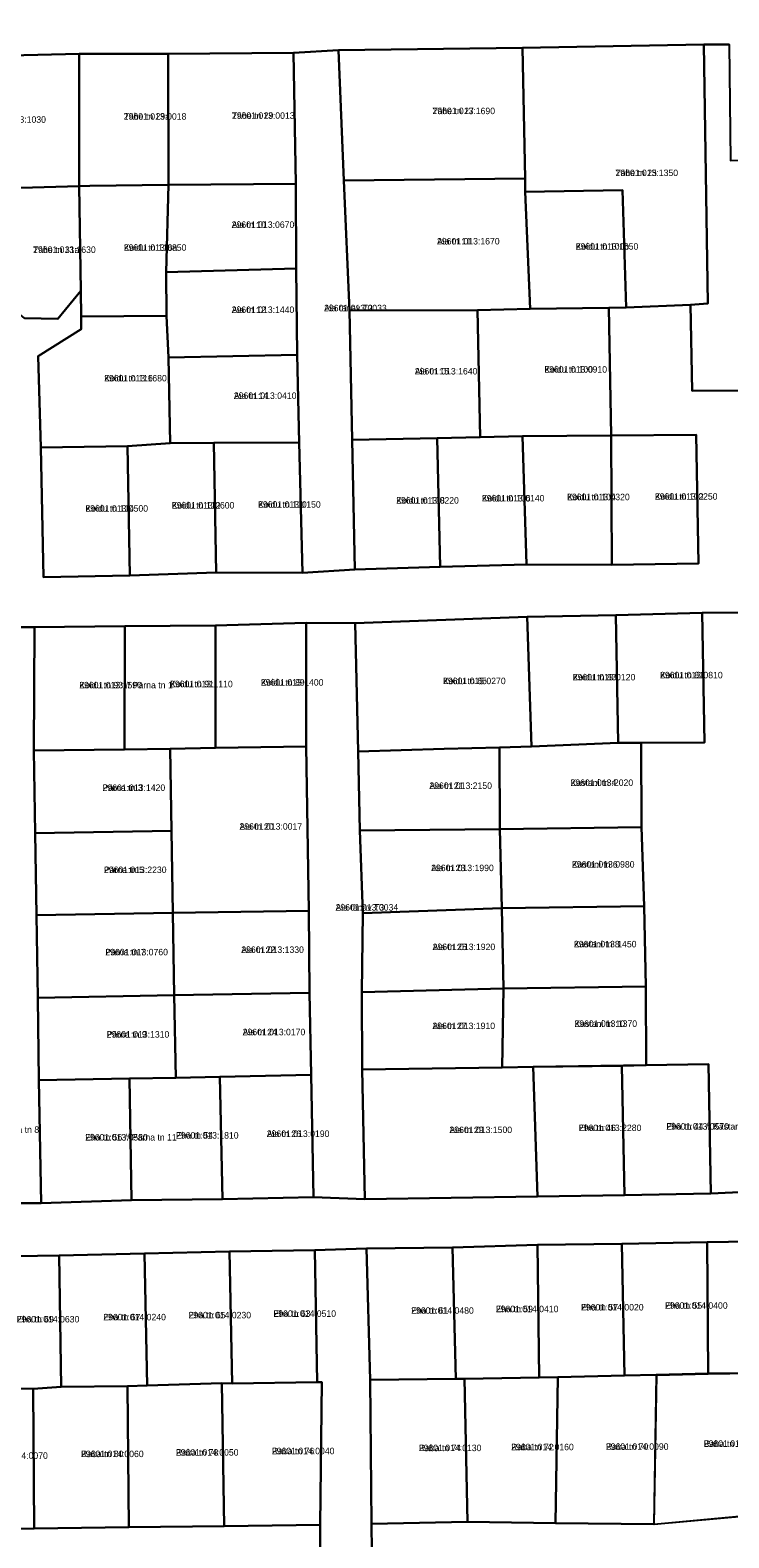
# Model space of a CAD drawing. Extents: x 518839 to 525192, y 6573164 to 6576561.
# Drawn here: x 523514.2 to 523676, y 6573652.7 to 6574001.8 of the extents above; entities that cross this region are included whole.
import ezdxf

# ---------------------------------------------------------------- set-up
doc = ezdxf.new("R2010")
doc.units = 0
for name, color, linetype in [('L_AADRESS', 7, 'Continuous'), ('PIIR', 7, 'Continuous'), ('TUNNUS', 7, 'Continuous')]:
    doc.layers.add(name, color=color, linetype=linetype)

msp = doc.modelspace()

# ---------------------------------------------------------------- linework, layer by layer
at = {"layer": 'PIIR'}
for points in [[(523676.04, 6573998.47), (523670.16, 6573998.46), (523628.17, 6573997.67), (523585.64, 6573997.1), (523575.15, 6573996.53), (523546.14, 6573996.29), (523525.52, 6573996.29), (523480.74, 6573995.19), (523455.07, 6573994.57), (523435.27, 6573993.85), (523414.5, 6573993.67), (523371.79, 6573992.85), (523370.33, 6574007.54)], [(523512.9, 6573935.07), (523520.6, 6573934.94), (523525.92, 6573941.42), (523526.01, 6573935.47), (523525.98, 6573932.52), (523516.07, 6573926.28), (523516.7, 6573905.14), (523517.3, 6573875.11), (523537.3, 6573875.48), (523557.26, 6573876.22), (523577.26, 6573876.13), (523589.39, 6573876.9), (523609.17, 6573877.54), (523629.13, 6573878.07), (523648.89, 6573878), (523669, 6573878.25), (523668.45, 6573908.07), (523648.73, 6573907.92), (523648.2, 6573937.46), (523652.2, 6573937.52), (523667.09, 6573938.18), (523667.5, 6573918.29), (523684.56, 6573918.33)], [(523680.81, 6573866.98), (523669.79, 6573866.9), (523649.8, 6573866.3), (523629.31, 6573865.94), (523589.48, 6573864.46), (523578.15, 6573864.54), (523557.15, 6573863.96), (523536.12, 6573863.76), (523515.24, 6573863.54), (523505.5, 6573863.51)], [(523507.79, 6573730.18), (523516.72, 6573730.15), (523537.69, 6573730.88), (523558.72, 6573731.15), (523579.85, 6573731.54), (523591.71, 6573731.11), (523631.71, 6573731.73), (523651.79, 6573732.03), (523671.79, 6573732.4), (523683.56, 6573732.98)], [(523690.66, 6573721.47), (523670.95, 6573721.16), (523651.22, 6573720.81), (523631.65, 6573720.51), (523611.99, 6573719.95), (523592.12, 6573719.66), (523580.11, 6573719.33), (523560.38, 6573718.97), (523540.72, 6573718.56), (523520.95, 6573718.1), (523500.82, 6573717.74)]]:
    msp.add_lwpolyline(points, dxfattribs=at)
for points in [[(523575.15, 6573996.53), (523585.64, 6573997.1), (523586.81, 6573966.96), (523588.13, 6573936.85), (523588.77, 6573906.88), (523589.39, 6573876.9), (523577.26, 6573876.13), (523576.53, 6573906.29), (523576.07, 6573926.61), (523575.82, 6573946.61), (523575.71, 6573966.2)], [(523585.64, 6573997.1), (523628.17, 6573997.67), (523628.8, 6573967.45), (523586.81, 6573966.96)], [(523651.37, 6573964.72), (523628.86, 6573964.36), (523628.8, 6573967.45), (523628.17, 6573997.67), (523670.16, 6573998.46), (523671.15, 6573938.46), (523667.09, 6573938.18), (523652.2, 6573937.52)], [(523670.16, 6573998.46), (523676.04, 6573998.47), (523676.34, 6573971.58), (523712.69, 6573972.67), (523712.7, 6573966.98), (523713.63, 6573939.28), (523699.65, 6573938.45), (523700.01, 6573925.48), (523684.56, 6573918.33), (523667.5, 6573918.29), (523667.09, 6573938.18), (523671.15, 6573938.46)], [(523480.74, 6573995.19), (523525.52, 6573996.29), (523525.53, 6573965.66), (523503.85, 6573965.03), (523481.7, 6573964.38)], [(523546.14, 6573996.29), (523546.24, 6573965.93), (523528.03, 6573965.71), (523525.53, 6573965.66), (523525.52, 6573996.29)], [(523575.15, 6573996.53), (523575.71, 6573966.2), (523546.24, 6573965.93), (523546.14, 6573996.29)], [(523505.33, 6573941.1), (523503.85, 6573965.03), (523525.53, 6573965.66), (523525.92, 6573941.42), (523520.6, 6573934.94), (523512.9, 6573935.07)], [(523525.92, 6573941.42), (523525.53, 6573965.66), (523528.03, 6573965.71), (523546.24, 6573965.93), (523545.71, 6573945.77), (523545.8, 6573935.63), (523526.01, 6573935.47)], [(523575.82, 6573946.61), (523545.71, 6573945.77), (523546.24, 6573965.93), (523575.71, 6573966.2)], [(523586.81, 6573966.96), (523628.8, 6573967.45), (523628.86, 6573964.36), (523629.98, 6573937.21), (523617.78, 6573936.97), (523588.13, 6573936.85)], [(523628.86, 6573964.36), (523651.37, 6573964.72), (523652.2, 6573937.52), (523648.2, 6573937.46), (523629.98, 6573937.21)], [(523545.8, 6573935.63), (523545.71, 6573945.77), (523575.82, 6573946.61), (523576.07, 6573926.61), (523546.27, 6573925.97)], [(523516.07, 6573926.28), (523525.98, 6573932.52), (523526.01, 6573935.47), (523545.8, 6573935.63), (523546.27, 6573925.97), (523546.61, 6573906.17), (523536.75, 6573905.46), (523516.7, 6573905.14)], [(523588.13, 6573936.85), (523617.78, 6573936.97), (523618.4, 6573907.5), (523608.47, 6573907.29), (523588.77, 6573906.88)], [(523618.4, 6573907.5), (523617.78, 6573936.97), (523629.98, 6573937.21), (523648.2, 6573937.46), (523648.73, 6573907.92), (523628.19, 6573907.76)], [(523546.61, 6573906.17), (523546.27, 6573925.97), (523576.07, 6573926.61), (523576.53, 6573906.29), (523556.71, 6573906.21)], [(523546.61, 6573906.17), (523556.71, 6573906.21), (523557.26, 6573876.22), (523537.3, 6573875.48), (523536.75, 6573905.46)], [(523556.71, 6573906.21), (523576.53, 6573906.29), (523577.26, 6573876.13), (523557.26, 6573876.22)], [(523588.77, 6573906.88), (523608.47, 6573907.29), (523609.17, 6573877.54), (523589.39, 6573876.9)], [(523608.47, 6573907.29), (523618.4, 6573907.5), (523628.19, 6573907.76), (523629.13, 6573878.07), (523609.17, 6573877.54)], [(523628.19, 6573907.76), (523648.73, 6573907.92), (523648.89, 6573878), (523629.13, 6573878.07)], [(523648.73, 6573907.92), (523668.45, 6573908.07), (523669, 6573878.25), (523648.89, 6573878)], [(523517.3, 6573875.11), (523516.7, 6573905.14), (523526.75, 6573905.28), (523536.75, 6573905.46), (523537.3, 6573875.48)], [(523557.15, 6573863.96), (523578.15, 6573864.54), (523578.13, 6573835.94), (523557.1, 6573835.59)], [(523578.15, 6573864.54), (523589.48, 6573864.46), (523590.14, 6573834.75), (523590.58, 6573816.5), (523591.2, 6573797.32), (523591.04, 6573779.03), (523591.09, 6573761.1), (523591.71, 6573731.11), (523579.85, 6573731.54), (523579.26, 6573759.91), (523578.86, 6573778.88), (523578.76, 6573797.9), (523578.44, 6573816.92), (523578.13, 6573835.94)], [(523589.48, 6573864.46), (523629.31, 6573865.94), (523630.3, 6573835.92), (523622.87, 6573835.7), (523610.06, 6573835.34), (523590.14, 6573834.75)], [(523629.31, 6573865.94), (523649.8, 6573866.3), (523650.34, 6573836.76), (523630.3, 6573835.92)], [(523650.34, 6573836.76), (523649.8, 6573866.3), (523669.79, 6573866.9), (523670.33, 6573836.83), (523655.68, 6573836.78)], [(523669.79, 6573866.9), (523680.81, 6573866.98), (523681.09, 6573836.98), (523696.74, 6573837.13), (523697, 6573818.44), (523697.67, 6573799.99), (523697.75, 6573781.23), (523698.04, 6573763.28), (523682.95, 6573762.72), (523683.56, 6573732.98), (523671.79, 6573732.4), (523671.24, 6573762.39), (523656.86, 6573762.12), (523656.77, 6573780.37), (523656.38, 6573798.96), (523655.8, 6573817.24), (523655.68, 6573836.78), (523670.33, 6573836.83)], [(523418.77, 6573799.99), (523439.53, 6573800.47), (523464.67, 6573800.57), (523481.77, 6573800.88), (523503.2, 6573801.82), (523502.82, 6573830.27), (523505.95, 6573830.39), (523505.5, 6573863.51), (523515.24, 6573863.54), (523515.05, 6573835.01), (523515.36, 6573815.85), (523515.68, 6573796.84), (523516, 6573777.76), (523516.2, 6573758.68), (523516.72, 6573730.15), (523507.79, 6573730.18), (523507.17, 6573763.2), (523506.82, 6573791.66), (523471.42, 6573791.21), (523439.93, 6573790.32), (523418.85, 6573789.88)], [(523515.24, 6573863.54), (523536.12, 6573863.76), (523536.08, 6573835.23), (523515.05, 6573835.01)], [(523536.08, 6573835.23), (523536.12, 6573863.76), (523557.15, 6573863.96), (523557.1, 6573835.59), (523546.59, 6573835.41)], [(523622.87, 6573835.7), (523630.3, 6573835.92), (523650.34, 6573836.76), (523655.68, 6573836.78), (523655.8, 6573817.24), (523622.99, 6573816.8)], [(523515.05, 6573835.01), (523536.08, 6573835.23), (523546.59, 6573835.41), (523546.91, 6573816.39), (523515.36, 6573815.85)], [(523578.13, 6573835.94), (523578.44, 6573816.92), (523578.76, 6573797.9), (523547.22, 6573797.38), (523546.91, 6573816.39), (523546.59, 6573835.41), (523557.1, 6573835.59)], [(523590.14, 6573834.75), (523610.06, 6573835.34), (523622.87, 6573835.7), (523622.99, 6573816.8), (523590.58, 6573816.5)], [(523515.36, 6573815.85), (523546.91, 6573816.39), (523547.22, 6573797.38), (523515.68, 6573796.84)], [(523590.58, 6573816.5), (523622.99, 6573816.8), (523623.44, 6573798.52), (523591.2, 6573797.32)], [(523622.99, 6573816.8), (523655.8, 6573817.24), (523656.38, 6573798.96), (523623.44, 6573798.52)], [(523591.2, 6573797.32), (523623.44, 6573798.52), (523623.84, 6573779.88), (523591.04, 6573779.03)], [(523623.44, 6573798.52), (523656.38, 6573798.96), (523656.77, 6573780.37), (523623.84, 6573779.88)], [(523515.68, 6573796.84), (523547.22, 6573797.38), (523547.54, 6573778.36), (523516, 6573777.76)], [(523547.22, 6573797.38), (523578.76, 6573797.9), (523578.86, 6573778.88), (523547.54, 6573778.36)], [(523516, 6573777.76), (523547.54, 6573778.36), (523547.96, 6573759.24), (523537.23, 6573759.07), (523516.2, 6573758.68)], [(523547.96, 6573759.24), (523547.54, 6573778.36), (523578.86, 6573778.88), (523579.26, 6573759.91), (523558.15, 6573759.46)], [(523591.04, 6573779.03), (523623.84, 6573779.88), (523623.48, 6573761.63), (523591.09, 6573761.1)], [(523623.48, 6573761.63), (523623.84, 6573779.88), (523656.77, 6573780.37), (523656.86, 6573762.12), (523630.67, 6573761.73)], [(523558.15, 6573759.46), (523579.26, 6573759.91), (523579.85, 6573731.54), (523558.72, 6573731.15)], [(523591.09, 6573761.1), (523623.48, 6573761.63), (523630.67, 6573761.73), (523631.71, 6573731.73), (523591.71, 6573731.11)], [(523630.67, 6573761.73), (523651.24, 6573762.02), (523651.79, 6573732.03), (523631.71, 6573731.73)], [(523671.79, 6573732.4), (523651.79, 6573732.03), (523651.24, 6573762.02), (523656.86, 6573762.12), (523671.24, 6573762.39)], [(523516.2, 6573758.68), (523537.23, 6573759.07), (523537.69, 6573730.88), (523516.72, 6573730.15)], [(523547.96, 6573759.24), (523558.15, 6573759.46), (523558.72, 6573731.15), (523537.69, 6573730.88), (523537.23, 6573759.07)], [(523651.84, 6573690.26), (523651.22, 6573720.81), (523670.95, 6573721.16), (523671.2, 6573690.74), (523659.19, 6573690.44)], [(523690.66, 6573721.47), (523691.16, 6573690.92), (523671.2, 6573690.74), (523670.95, 6573721.16)], [(523500.82, 6573717.74), (523520.95, 6573718.1), (523521.36, 6573687.69), (523514.89, 6573687.17), (523501.64, 6573687.34)], [(523520.95, 6573718.1), (523540.72, 6573718.56), (523541.32, 6573687.99), (523536.76, 6573687.85), (523521.36, 6573687.69)], [(523540.72, 6573718.56), (523560.38, 6573718.97), (523561, 6573688.44), (523558.6, 6573688.51), (523541.32, 6573687.99)], [(523560.38, 6573718.97), (523580.11, 6573719.33), (523580.67, 6573688.72), (523561, 6573688.44)], [(523580.11, 6573719.33), (523592.12, 6573719.66), (523592.91, 6573689.25), (523593.28, 6573655.92), (523593.49, 6573636.97), (523594.95, 6573580.41), (523581.3, 6573556.55), (523601.22, 6573439.05), (523612.43, 6573377.27), (523600.45, 6573375.91), (523589.37, 6573436.97), (523576.69, 6573511.75), (523568.72, 6573558.79), (523582.84, 6573583.46), (523581.46, 6573636.75), (523581.36, 6573655.75), (523581.74, 6573688.74), (523580.67, 6573688.72)], [(523592.12, 6573719.66), (523611.99, 6573719.95), (523612.75, 6573689.49), (523592.91, 6573689.25)], [(523612.75, 6573689.49), (523611.99, 6573719.95), (523631.65, 6573720.51), (523632.06, 6573689.82), (523614.76, 6573689.51)], [(523632.06, 6573689.82), (523631.65, 6573720.51), (523651.22, 6573720.81), (523651.84, 6573690.26), (523636.4, 6573689.9)], [(523614.76, 6573689.51), (523632.06, 6573689.82), (523636.4, 6573689.9), (523635.86, 6573656.13), (523615.49, 6573656.39)], [(523636.4, 6573689.9), (523651.84, 6573690.26), (523659.19, 6573690.44), (523658.64, 6573655.87), (523635.86, 6573656.13)], [(523659.29, 6573690.4), (523671.2, 6573690.7), (523681.28, 6573690.84), (523681.65, 6573684.84), (523680.91, 6573657.85), (523658.7, 6573655.81)], [(523492.44, 6573686.99), (523501.64, 6573687.34), (523514.89, 6573687.17), (523515.17, 6573654.87), (523493.08, 6573654.49)], [(523514.89, 6573687.17), (523521.36, 6573687.69), (523536.76, 6573687.85), (523537.06, 6573655.2), (523515.17, 6573654.87)], [(523536.76, 6573687.85), (523541.32, 6573687.99), (523558.6, 6573688.51), (523559.13, 6573655.37), (523537.06, 6573655.2)], [(523561, 6573688.44), (523580.67, 6573688.72), (523581.74, 6573688.74), (523581.36, 6573655.75), (523559.13, 6573655.37), (523558.6, 6573688.51)], [(523592.91, 6573689.25), (523612.75, 6573689.49), (523614.76, 6573689.51), (523615.49, 6573656.39), (523593.28, 6573655.92)], [(523593.49, 6573636.97), (523593.28, 6573655.92), (523615.49, 6573656.39), (523635.86, 6573656.13), (523658.64, 6573655.87), (523680.91, 6573657.85), (523724.95, 6573658.79), (523767.3, 6573659.07), (523797.87, 6573659.57), (523798.04, 6573641.63), (523731.73, 6573638.73), (523716.85, 6573638.54), (523702.51, 6573638.35), (523682.5, 6573638.09), (523633.32, 6573637.47)], [(523426.74, 6573634.12), (523427.01, 6573653.13), (523449.21, 6573653.56), (523471.1, 6573654.07), (523493.08, 6573654.49), (523515.17, 6573654.87), (523537.06, 6573655.2), (523559.13, 6573655.37), (523581.36, 6573655.75), (523581.46, 6573636.75)]]:
    msp.add_lwpolyline(points, close=True, dxfattribs=at)

# ---------------------------------------------------------------- texts
at = {"layer": 'L_AADRESS'}
for s, p in [('Tähe tn 27', (523607.35, 6573982.32)), ('Tähe tn 29a', (523535.88, 6573981.05)), ('Tähe tn 29', (523560.93, 6573981.24)), ('Tähe tn 25', (523649.73, 6573967.99)), ('Aia tn 10', (523560.87, 6573955.99)), ('Tähe tn 31a', (523514.89, 6573950.19)), ('Koidu tn 116a', (523535.89, 6573950.68)), ('Aia tn 11', (523608.41, 6573952.15)), ('Koidu tn 100b', (523640.53, 6573950.95)), ('Aia tn 12', (523560.87, 6573936.29)), ('Aia tänav T2', (523582.27, 6573936.68)), ('Aia tn 15', (523603.27, 6573922.05)), ('Koidu tn 100', (523633.28, 6573922.48)), ('Koidu tn 116', (523531.34, 6573920.44)), ('Aia tn 14', (523561.37, 6573916.39)), ('Koidu tn 112', (523547, 6573891.01)), ('Koidu tn 110', (523566.98, 6573891.21)), ('Koidu tn 108', (523598.97, 6573892.15)), ('Koidu tn 106', (523618.8, 6573892.65)), ('Koidu tn 104', (523638.54, 6573892.94)), ('Koidu tn 102', (523658.86, 6573893.06)), ('Koidu tn 114', (523527, 6573890.29)), ('Koidu tn 93 // Pärna tn 1', (523525.58, 6573849.38)), ('Koidu tn 91', (523546.61, 6573849.64)), ('Koidu tn 89', (523567.62, 6573850.01)), ('Koidu tn 85', (523609.81, 6573850.35)), ('Koidu tn 83', (523639.83, 6573851.22)), ('Koidu tn 81', (523660.06, 6573851.7)), ('Pärna tn 3', (523530.98, 6573825.63)), ('Aia tn 21', (523606.64, 6573826.1)), ('Kastani tn 4', (523639.33, 6573826.79)), ('Aia tn 20', (523562.68, 6573816.66)), ('Aia tn 23', (523607.06, 6573807.06)), ('Kastani tn 6', (523639.65, 6573807.88)), ('Pärna tn 5', (523531.29, 6573806.62)), ('Aia tänav T3', (523584.92, 6573797.92)), ('Kastani tn 8', (523640.11, 6573789.42)), ('Pärna tn 7', (523531.61, 6573787.57)), ('Aia tn 22', (523563.09, 6573788.13)), ('Aia tn 25', (523607.39, 6573788.78)), ('Pärna tn 9', (523531.93, 6573768.52)), ('Aia tn 24', (523563.41, 6573769.06)), ('Aia tn 27', (523607.36, 6573770.49)), ('Kastani tn 10', (523640.24, 6573771)), ('Eha tn 58 // Pärna tn 8', (523496.21, 6573746.47)), ('Eha tn 56 // Pärna tn 11', (523526.95, 6573744.69)), ('Eha tn 54', (523547.97, 6573745.13)), ('Aia tn 26', (523569, 6573745.52)), ('Aia tn 29', (523611.3, 6573746.42)), ('Eha tn 46', (523641.23, 6573746.88)), ('Eha tn 44 // Kastani tn 12', (523661.52, 6573747.21)), ('Eha tn 55', (523661.21, 6573705.74)), ('Eha tn 69', (523511.09, 6573702.57)), ('Eha tn 67', (523531.14, 6573703.06)), ('Eha tn 65', (523550.86, 6573703.52)), ('Eha tn 63', (523570.53, 6573703.87)), ('Eha tn 61', (523602.43, 6573704.59)), ('Eha tn 59', (523622.03, 6573704.94)), ('Eha tn 57', (523641.75, 6573705.34)), ('Raba tn 80', (523525.98, 6573671.39)), ('Raba tn 78', (523547.95, 6573671.74)), ('Raba tn 76', (523570.17, 6573672.06)), ('Raba tn 74', (523604.2, 6573672.77)), ('Raba tn 72', (523625.58, 6573672.98)), ('Raba tn 70', (523647.52, 6573673.08)), ('Raba tn 68', (523670.18, 6573673.77))]:
    msp.add_text(s, height=1.5, dxfattribs=at).set_placement(p)
at = {"layer": 'TUNNUS'}
for s, p in [('29601:013:1690', (523607.35, 6573982.32)), ('29601:013:1030', (523503.36, 6573980.33)), ('29601:013:0018', (523535.88, 6573981.05)), ('29601:013:0013', (523560.93, 6573981.24)), ('29601:013:1350', (523649.73, 6573967.99)), ('29601:013:0670', (523560.87, 6573955.99)), ('29601:013:1630', (523514.89, 6573950.19)), ('29601:013:0850', (523535.89, 6573950.68)), ('29601:013:1670', (523608.41, 6573952.15)), ('29601:013:1650', (523640.53, 6573950.95)), ('29601:013:1440', (523560.87, 6573936.29)), ('29601:013:0033', (523582.27, 6573936.68)), ('29601:013:0910', (523633.28, 6573922.48)), ('29601:013:1680', (523531.34, 6573920.44)), ('29601:013:1640', (523603.27, 6573922.05)), ('29601:013:0410', (523561.37, 6573916.39)), ('29601:013:0600', (523547, 6573891.01)), ('29601:013:1150', (523566.98, 6573891.21)), ('29601:013:0220', (523598.97, 6573892.15)), ('29601:013:0140', (523618.8, 6573892.65)), ('29601:013:0320', (523638.54, 6573892.94)), ('29601:013:0250', (523658.86, 6573893.06)), ('29601:013:0500', (523527, 6573890.29)), ('29601:013:1590', (523525.58, 6573849.38)), ('29601:013:1110', (523546.61, 6573849.64)), ('29601:013:1400', (523567.62, 6573850.01)), ('29601:013:0270', (523609.81, 6573850.35)), ('29601:013:0120', (523639.83, 6573851.22)), ('29601:013:0810', (523660.06, 6573851.7)), ('29601:013:1420', (523530.98, 6573825.63)), ('29601:013:2150', (523606.64, 6573826.1)), ('29601:013:2020', (523639.33, 6573826.79)), ('29601:013:0017', (523562.68, 6573816.66)), ('29601:013:1990', (523607.06, 6573807.06)), ('29601:013:0980', (523639.65, 6573807.88)), ('29601:013:2230', (523531.29, 6573806.62)), ('29601:013:0034', (523584.92, 6573797.92)), ('29601:013:0760', (523531.61, 6573787.57)), ('29601:013:1330', (523563.09, 6573788.13)), ('29601:013:1920', (523607.39, 6573788.78)), ('29601:013:1450', (523640.11, 6573789.42)), ('29601:013:1310', (523531.93, 6573768.52)), ('29601:013:0170', (523563.41, 6573769.06)), ('29601:013:1910', (523607.36, 6573770.49)), ('29601:013:1370', (523640.24, 6573771)), ('29601:013:0580', (523526.95, 6573744.69)), ('29601:013:1810', (523547.97, 6573745.13)), ('29601:013:0190', (523569, 6573745.52)), ('29601:013:1500', (523611.3, 6573746.42)), ('29601:013:2280', (523641.23, 6573746.88)), ('29601:013:0570', (523661.52, 6573747.21)), ('29601:014:0400', (523661.21, 6573705.74)), ('29601:014:0630', (523511.09, 6573702.57)), ('29601:014:0240', (523531.14, 6573703.06)), ('29601:014:0230', (523550.86, 6573703.52)), ('29601:014:0510', (523570.53, 6573703.87)), ('29601:014:0480', (523602.43, 6573704.59)), ('29601:014:0410', (523622.03, 6573704.94)), ('29601:014:0020', (523641.75, 6573705.34)), ('29601:014:0070', (523503.8, 6573670.99)), ('29601:014:0060', (523525.98, 6573671.39)), ('29601:014:0050', (523547.95, 6573671.74)), ('29601:014:0040', (523570.17, 6573672.06)), ('29601:014:0130', (523604.2, 6573672.77)), ('29601:014:0160', (523625.58, 6573672.98)), ('29601:014:0090', (523647.52, 6573673.08)), ('29601:014:0056', (523670.18, 6573673.77))]:
    msp.add_text(s, height=1.5, dxfattribs=at).set_placement(p)

doc.saveas('drawing.dxf')
